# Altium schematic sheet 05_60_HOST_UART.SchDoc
size 289 x 396 mm
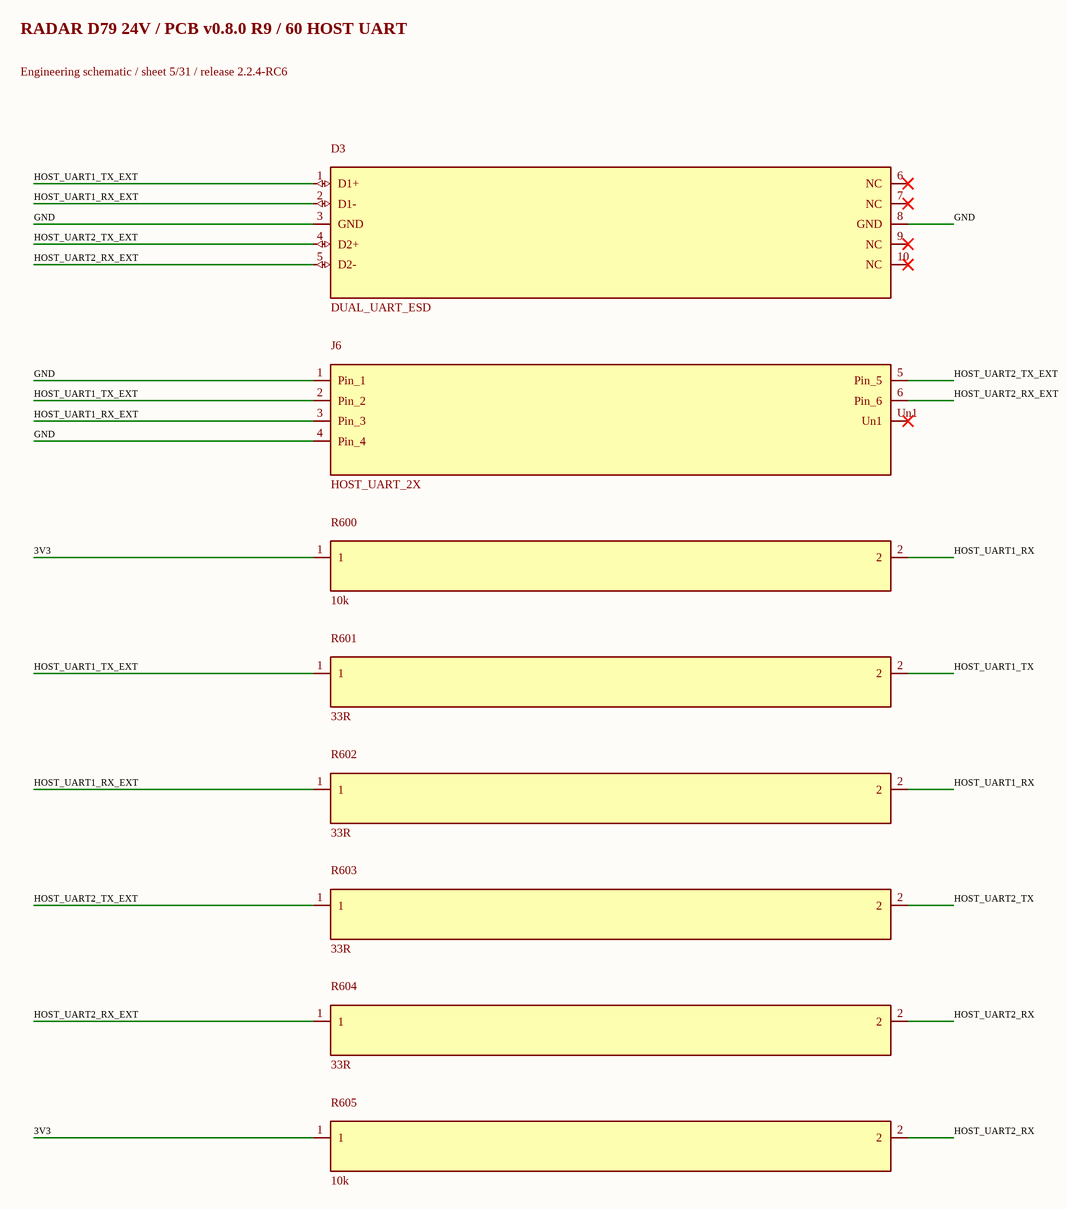
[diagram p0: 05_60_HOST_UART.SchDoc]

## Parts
D3  DUAL_UART_ESD  [USON-10_2.5x1.0mm_P0.5mm]
J6  HOST_UART_2X  [Molex_43045-0600_RA_THT_6P]
R600  10k  [R_0603_1608Metric]
R601  33R  [R_0402_1005Metric]
R602  33R  [R_0402_1005Metric]
R603  33R  [R_0402_1005Metric]
R604  33R  [R_0402_1005Metric]
R605  10k  [R_0603_1608Metric]

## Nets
3V3: R600.1 R605.1
GND: D3.3(GND) D3.8(GND) J6.1(Pin_1) J6.4(Pin_4)
HOST_UART1_RX: R600.2 R602.2
HOST_UART1_RX_EXT: D3.2(D1-) J6.3(Pin_3) R602.1
HOST_UART1_TX: R601.2
HOST_UART1_TX_EXT: D3.1(D1+) J6.2(Pin_2) R601.1
HOST_UART2_RX: R604.2 R605.2
HOST_UART2_RX_EXT: D3.5(D2-) J6.6(Pin_6) R604.1
HOST_UART2_TX: R603.2
HOST_UART2_TX_EXT: D3.4(D2+) J6.5(Pin_5) R603.1

Not connected (* = marked no-connect by the designer): D3 6(NC)* 7(NC)* 9(NC)* 10(NC)*; J6 Un1*

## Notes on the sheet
- RADAR D79 24V / PCB v0.8.0 R9 / 60 HOST UART
- Engineering schematic / sheet 5/31 / release 2.2.4-RC6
